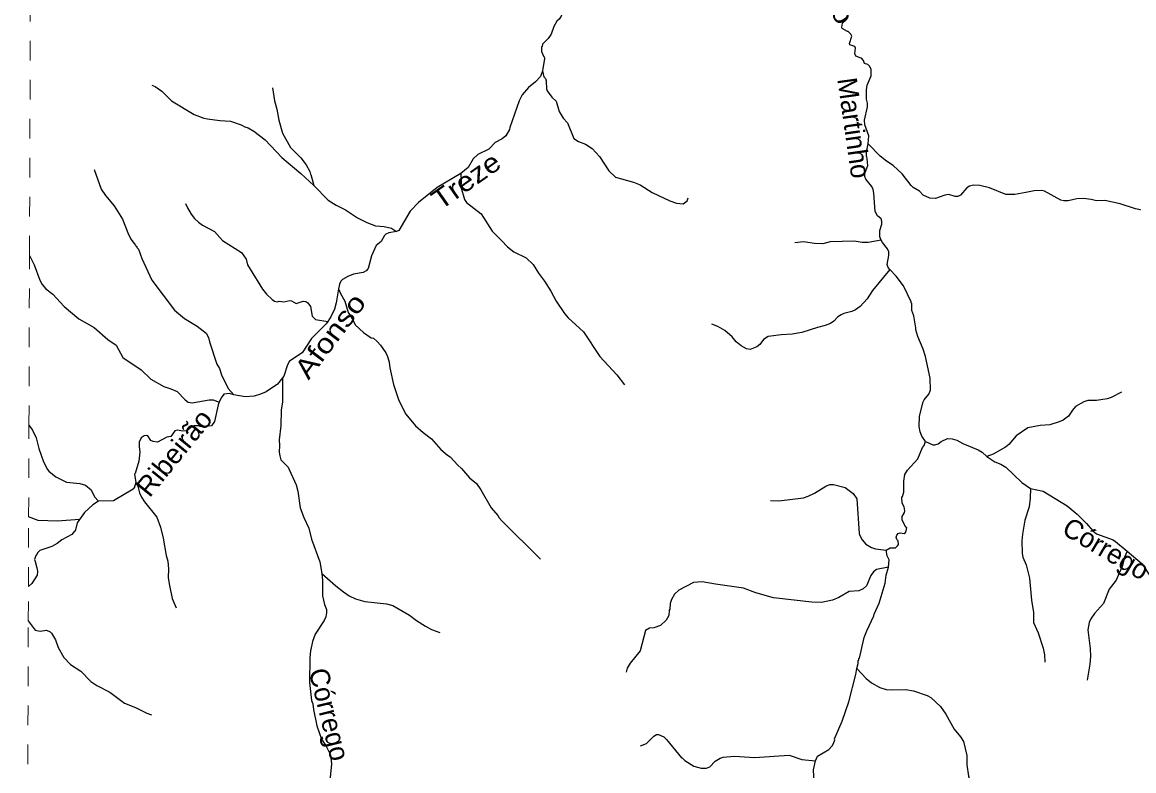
# Model space of a CAD drawing. Extents: x 551.6 to 577.6, y 7567 to 7594.7.
# Drawn here: x 551.61 to 557.32, y 7575.9 to 7579.74 of the extents above; entities that cross this region are included whole.
import ezdxf
from ezdxf.enums import TextEntityAlignment as Align

# ---------------------------------------------------------------- set-up
doc = ezdxf.new("R2010")
doc.units = 0
doc.header["$LTSCALE"] = 0.04
doc.linetypes.add('SHORT_DASHED', pattern=[2.7, 1.5, -1.2])
doc.layers.add('53', color=7, linetype='SHORT_DASHED', lineweight=13)
doc.layers.add('7', color=7, linetype='Continuous', lineweight=25)
doc.layers.add('61', color=7, linetype='Continuous')

msp = doc.modelspace()

# ---------------------------------------------------------------- linework, layer by layer
at = {"layer": '53'}
msp.add_lwpolyline([(551.613, 7567.0572), (551.6165, 7568.1281), (551.6253, 7570.846), (551.6259, 7571.0339), (551.6348, 7573.7652), (551.6406, 7575.5319), (551.6443, 7576.6663), (551.6448, 7576.8423), (551.646, 7577.1998), (551.6475, 7577.6707), (551.6503, 7578.541), (551.6589, 7581.176)], dxfattribs=at)
at = {"layer": '7'}
for points in [[(555.9119, 7579.5547), (555.8885, 7579.5627), (555.8837, 7579.5764), (555.8877, 7579.6038), (555.8845, 7579.6127), (555.8579, 7579.6215), (555.8563, 7579.6271), (555.8692, 7579.665), (555.8644, 7579.6746), (555.8507, 7579.6883), (555.8458, 7579.6883), (555.8193, 7579.7044), (555.8169, 7579.7116), (555.8201, 7579.7326), (555.8386, 7579.747), (555.8483, 7579.7599), (555.8491, 7579.78), (555.8418, 7579.8034), (555.8644, 7579.8404), (555.8644, 7579.8501), (555.8528, 7579.8734)], [(554.3837, 7579.7851), (554.3771, 7579.768), (554.3674, 7579.7527), (554.3562, 7579.7422), (554.3401, 7579.7149), (554.3272, 7579.6762), (554.3103, 7579.6529), (554.2821, 7579.6247), (554.2805, 7579.6127), (554.2773, 7579.6102), (554.2773, 7579.5869), (554.287, 7579.5628), (554.291, 7579.5595), (554.2918, 7579.5507), (554.2818, 7579.4878)], [(555.9532, 7579.1125), (555.9561, 7579.1547), (555.9352, 7579.2111), (555.9336, 7579.2352), (555.9497, 7579.3028), (555.9489, 7579.3221), (555.9432, 7579.3414), (555.944, 7579.3897), (555.9481, 7579.4139), (555.9674, 7579.4622), (555.9674, 7579.4944), (555.9609, 7579.5104), (555.9513, 7579.5201), (555.9336, 7579.5257), (555.9288, 7579.541), (555.9183, 7579.5531), (555.9119, 7579.5547)], [(554.2818, 7579.4878), (554.2725, 7579.4589), (554.2459, 7579.4307), (554.2105, 7579.4026), (554.1783, 7579.364), (554.163, 7579.3342), (554.1147, 7579.1966)], [(554.2818, 7579.4878), (554.2886, 7579.4573), (554.2974, 7579.4477), (554.3015, 7579.4364), (554.3031, 7579.3946), (554.3063, 7579.3849), (554.3296, 7579.3527), (554.3513, 7579.3318), (554.3674, 7579.2787), (554.3884, 7579.2449), (554.4101, 7579.2207), (554.4431, 7579.141), (554.4664, 7579.1257), (554.5027, 7579.1121), (554.5365, 7579.0887), (554.5735, 7579.0485), (554.6226, 7578.9745), (554.6572, 7578.9422), (554.7489, 7578.9165), (554.7827, 7578.902), (554.8439, 7578.8642), (554.9357, 7578.8207)], [(552.2774, 7579.4131), (552.2943, 7579.4066), (552.3297, 7579.3833), (552.378, 7579.3334), (552.4955, 7579.2634), (552.5438, 7579.2448), (552.5631, 7579.2408), (552.6259, 7579.2328), (552.6822, 7579.2295), (552.7361, 7579.2102), (552.7546, 7579.1998), (552.7723, 7579.1958), (552.8013, 7579.178), (552.8585, 7579.133), (552.9454, 7579.0428), (553.0428, 7578.9616), (553.1082, 7578.9001), (553.1828, 7578.8248)], [(552.8971, 7579.4002), (552.9075, 7579.3334), (552.9188, 7579.2915), (552.9285, 7579.2352), (552.9486, 7579.1676), (552.9896, 7579.0936), (553.0419, 7579.0412), (553.0693, 7579.005), (553.0878, 7578.9712), (553.091, 7578.9567), (553.0943, 7578.9551), (553.1082, 7578.9001)], [(554.1147, 7579.1966), (554.1131, 7579.1861), (554.0946, 7579.1539), (554.0745, 7579.1386), (554.0399, 7579.1193), (554.0069, 7579.0863), (553.9497, 7579.0589), (553.9256, 7579.0356), (553.9007, 7578.9921), (553.8627, 7578.9606)], [(555.9819, 7578.8602), (555.9787, 7578.8795), (555.9714, 7578.894), (555.94, 7578.931), (555.9352, 7578.9455), (555.9352, 7578.9608), (555.9505, 7579.0018), (555.9481, 7579.0356), (555.9457, 7579.0469), (555.9432, 7579.0477), (555.9432, 7579.0726), (555.9532, 7579.1125)], [(556.7609, 7578.8642), (556.7046, 7578.8537), (556.6595, 7578.8537), (556.5742, 7578.8875), (556.5259, 7578.8988), (556.4921, 7578.9012), (556.4728, 7578.8964), (556.4583, 7578.8867), (556.4261, 7578.8497), (556.4124, 7578.8433), (556.398, 7578.8433), (556.3666, 7578.8537), (556.3457, 7578.8505), (556.2974, 7578.832), (556.2684, 7578.8352), (556.2346, 7578.8497), (556.2161, 7578.8698), (556.1831, 7578.8899), (556.1726, 7578.8996), (556.1267, 7578.9592), (556.0809, 7579.0018), (556.0463, 7579.0235), (556.0133, 7579.0501), (555.9532, 7579.1125)], [(551.9828, 7578.9809), (552.0174, 7578.8811), (552.04, 7578.8481), (552.085, 7578.7942), (552.1277, 7578.7266), (552.1583, 7578.6477), (552.1711, 7578.6227), (552.1848, 7578.6034), (552.1881, 7578.6034), (552.1913, 7578.5946), (552.1945, 7578.5946), (552.1961, 7578.5889), (552.2009, 7578.5857), (552.2009, 7578.5809), (552.209, 7578.572), (552.2259, 7578.5254), (552.2774, 7578.4143), (552.3933, 7578.2598), (552.4456, 7578.2179), (552.51, 7578.1777), (552.5566, 7578.1423), (552.5679, 7578.1198), (552.5744, 7578.0972)], [(553.8627, 7578.9606), (553.7413, 7578.8891), (553.6455, 7578.8127), (553.6037, 7578.7684), (553.545, 7578.6694), (553.533, 7578.6635)], [(553.8627, 7578.9606), (553.8654, 7578.9212), (553.8631, 7578.8919), (553.8813, 7578.828), (553.8918, 7578.8127), (553.9675, 7578.7547), (554.0238, 7578.6646), (554.0721, 7578.6179), (554.1019, 7578.5841), (554.1341, 7578.5583), (554.1976, 7578.5286), (554.2346, 7578.4948), (554.2612, 7578.4505), (554.2926, 7578.4095), (554.3248, 7578.358), (554.3513, 7578.3057), (554.3948, 7578.2421), (554.4133, 7578.2203), (554.4713, 7578.1672)], [(553.1828, 7578.8248), (553.223, 7578.7982), (553.2713, 7578.7748), (553.3333, 7578.733), (553.3808, 7578.7088), (553.4258, 7578.6928), (553.4693, 7578.6895), (553.5079, 7578.6799), (553.533, 7578.6635)], [(554.9357, 7578.8207), (554.9695, 7578.8095), (555.0033, 7578.8046), (555.0242, 7578.8199), (555.029, 7578.8368)], [(556.0199, 7578.6198), (556.0125, 7578.6364), (556.0125, 7578.6686), (556.0221, 7578.7008), (556.0221, 7578.7169), (556.0189, 7578.729), (556.0004, 7578.7435), (555.9883, 7578.7652), (555.9819, 7578.8602)], [(557.4766, 7578.756), (557.457, 7578.7549), (557.4225, 7578.7587), (557.3243, 7578.7797), (557.2454, 7578.8046), (557.1666, 7578.8223), (557.1247, 7578.8207), (557.0957, 7578.828), (557.0571, 7578.8328), (557.0233, 7578.8312), (556.9782, 7578.8199), (556.9557, 7578.8207), (556.9404, 7578.8247), (556.8567, 7578.8698), (556.843, 7578.873), (556.8044, 7578.8722), (556.7609, 7578.8642)], [(552.4512, 7578.8062), (552.4601, 7578.7845), (552.4802, 7578.7523), (552.4963, 7578.7298), (552.518, 7578.7105), (552.5374, 7578.696), (552.5985, 7578.663), (552.6404, 7578.6171), (552.7385, 7578.5551), (552.7611, 7578.5213), (552.7691, 7578.4932), (552.782, 7578.4706), (552.8456, 7578.3676), (552.8657, 7578.3419), (552.8955, 7578.3153), (552.9075, 7578.3056), (552.9204, 7578.3032), (552.9317, 7578.3064), (552.9542, 7578.3032), (552.9864, 7578.3089), (552.9945, 7578.3073), (553.0186, 7578.2936), (553.054, 7578.3064), (553.0677, 7578.3048), (553.0774, 7578.2984), (553.091, 7578.2791), (553.1007, 7578.2292), (553.1176, 7578.2123), (553.1804, 7578.2022)], [(553.533, 7578.6635), (553.4935, 7578.6573), (553.4789, 7578.6501), (553.4717, 7578.6429), (553.4548, 7578.6115), (553.429, 7578.5922), (553.4049, 7578.5383), (553.3872, 7578.4738), (553.3768, 7578.461), (553.3615, 7578.4529), (553.3132, 7578.4441), (553.2826, 7578.4328), (553.256, 7578.4167), (553.2472, 7578.4079), (553.2399, 7578.3934), (553.2355, 7578.3702), (553.2278, 7578.329)], [(556.0199, 7578.6198), (555.9529, 7578.6074), (555.9223, 7578.6074), (555.8805, 7578.6147), (555.7582, 7578.6099), (555.7195, 7578.6002), (555.6777, 7578.6018), (555.6213, 7578.6099), (555.5771, 7578.6059)], [(556.0631, 7578.4677), (556.0551, 7578.4787), (556.0495, 7578.4948), (556.0591, 7578.5399), (556.0591, 7578.5592), (556.0519, 7578.5753), (556.0253, 7578.6075), (556.0199, 7578.6198)], [(551.6503, 7578.541), (551.6746, 7578.4932), (551.7028, 7578.4143), (551.7148, 7578.3918), (551.7342, 7578.37), (551.7696, 7578.3419), (551.8283, 7578.2791), (551.9032, 7578.2147), (551.982, 7578.1704), (552.0529, 7578.1101), (552.0947, 7578.0803), (552.1293, 7578.0167), (552.2235, 7577.9548), (552.2726, 7577.9065), (552.3394, 7577.8686), (552.3748, 7577.8574), (552.407, 7577.8421), (552.4488, 7577.8002), (552.4649, 7577.789), (552.4842, 7577.7841)], [(556.0631, 7578.4677), (555.9754, 7578.3612), (555.9481, 7578.3177), (555.9119, 7578.2791), (555.8869, 7578.2614), (555.8692, 7578.2533), (555.8274, 7578.2421), (555.8137, 7578.2356), (555.7968, 7578.2252), (555.7759, 7578.2034), (555.7598, 7578.1922), (555.7324, 7578.1809), (555.6922, 7578.1712), (555.6117, 7578.1455), (555.5634, 7578.1374), (555.5055, 7578.1342), (555.4403, 7578.1246), (555.4153, 7578.1093), (555.3968, 7578.0843), (555.3815, 7578.0722), (555.3477, 7578.0586), (555.3284, 7578.0618), (555.301, 7578.0763)], [(556.1976, 7578.1697), (556.1863, 7578.2308), (556.1766, 7578.2582), (556.1766, 7578.2944), (556.1734, 7578.2968), (556.1734, 7578.3032), (556.1332, 7578.3853), (556.097, 7578.4336), (556.0631, 7578.4677)], [(553.2355, 7578.3702), (553.2456, 7578.3451), (553.2681, 7578.3065), (553.285, 7578.2485), (553.3091, 7578.2099), (553.3212, 7578.1841), (553.3631, 7578.1455), (553.4025, 7578.1189), (553.4146, 7578.1157), (553.4331, 7578.0996), (553.4508, 7578.0811), (553.4781, 7578.0409), (553.487, 7578.0216), (553.495, 7577.9926), (553.4983, 7577.9636), (553.5176, 7577.8783), (553.5457, 7577.7962), (553.5804, 7577.7262), (553.6303, 7577.6674), (553.6697, 7577.632), (553.7123, 7577.6006), (553.7606, 7577.5459), (553.7952, 7577.517)], [(553.2278, 7578.329), (553.2238, 7578.2968), (553.215, 7578.2646), (553.1973, 7578.2284), (553.1804, 7578.2022)], [(553.1804, 7578.2022), (553.1723, 7578.1897), (553.0975, 7578.1149), (553.0492, 7578.0417), (552.9848, 7577.9982), (552.9743, 7577.9797), (552.9542, 7577.9218), (552.9478, 7577.9124)], [(554.4713, 7578.1672), (554.4914, 7578.1487), (554.5767, 7578.0224), (554.6628, 7577.929), (554.7031, 7577.8775)], [(555.301, 7578.0763), (555.2761, 7578.0972), (555.2543, 7578.123), (555.2181, 7578.156), (555.1811, 7578.1769), (555.1505, 7578.1874)], [(556.2473, 7577.5872), (556.2273, 7577.6143), (556.2185, 7577.6353), (556.2137, 7577.6642), (556.2153, 7577.7165), (556.2346, 7577.7898), (556.2394, 7577.8002), (556.2644, 7577.8284), (556.2716, 7577.8493), (556.27, 7577.9121), (556.2467, 7578.0216), (556.2346, 7578.0602), (556.2072, 7578.1246), (556.1976, 7578.1584), (556.1976, 7578.1697)], [(552.5744, 7578.0972), (552.6114, 7577.9829), (552.6242, 7577.9604), (552.6347, 7577.9282), (552.6701, 7577.859), (552.6991, 7577.8264)], [(552.9478, 7577.9124), (552.922, 7577.8799), (552.8641, 7577.8413), (552.8351, 7577.8284), (552.8029, 7577.8187), (552.7563, 7577.8155), (552.6991, 7577.8264)], [(552.9478, 7577.9124), (552.9478, 7577.7882), (552.9413, 7577.7495), (552.9397, 7577.6675), (552.9309, 7577.5942), (552.9333, 7577.5661), (552.9317, 7577.5323), (552.9349, 7577.5129), (552.9397, 7577.4928), (552.9768, 7577.455), (552.9832, 7577.4437), (553.0178, 7577.3649), (553.0266, 7577.3311), (553.0395, 7577.2457), (553.0572, 7577.1975), (553.083, 7577.1427), (553.0975, 7577.0864), (553.1393, 7576.9689), (553.1501, 7576.9091)], [(552.4842, 7577.7841), (552.5728, 7577.8002), (552.5921, 7577.7994), (552.6233, 7577.788)], [(552.6991, 7577.8264), (552.6758, 7577.8332), (552.6468, 7577.83), (552.6331, 7577.8107), (552.6233, 7577.788)], [(557.2527, 7577.8397), (557.1988, 7577.8123), (557.1794, 7577.8059), (557.1247, 7577.797), (557.0796, 7577.797), (557.0587, 7577.7906), (557.0168, 7577.7656), (557.0008, 7577.7479), (556.9798, 7577.7165), (556.9525, 7577.6956), (556.9332, 7577.6868), (556.8849, 7577.6723), (556.835, 7577.669), (556.7722, 7577.6562), (556.7118, 7577.6159), (556.674, 7577.5709), (556.6579, 7577.5572), (556.5935, 7577.5218), (556.5618, 7577.5095)], [(552.6233, 7577.788), (552.6178, 7577.7753), (552.6001, 7577.6884), (552.584, 7577.6674), (552.5551, 7577.6626), (552.5261, 7577.6642), (552.518, 7577.6674), (552.4939, 7577.6666), (552.4778, 7577.6578), (552.4593, 7577.6409), (552.4376, 7577.6401), (552.4086, 7577.6441), (552.3957, 7577.6417), (552.3748, 7577.6127), (552.3555, 7577.6087)], [(551.6475, 7577.6707), (551.6649, 7577.6449), (551.6842, 7577.6047), (551.6987, 7577.55), (551.7213, 7577.4824), (551.7422, 7577.4437), (551.7502, 7577.4349), (551.7857, 7577.4059), (551.8404, 7577.3777), (551.908, 7577.3713), (551.937, 7577.3632), (551.9659, 7577.3391), (551.9836, 7577.3021), (552.0043, 7577.2799)], [(552.3555, 7577.6087), (552.3072, 7577.5837), (552.2854, 7577.5862), (552.2726, 7577.591), (552.2581, 7577.6151), (552.2525, 7577.6167), (552.2388, 7577.6159), (552.2234, 7577.6047), (552.2122, 7577.5829), (552.2122, 7577.5612), (552.217, 7577.5323), (552.2114, 7577.4856), (552.1929, 7577.4228), (552.1897, 7577.4196), (552.1952, 7577.3762)], [(556.1283, 7577.3037), (556.1348, 7577.3262), (556.1348, 7577.3826), (556.1412, 7577.4164), (556.1541, 7577.4389), (556.2072, 7577.4968), (556.2314, 7577.5564), (556.2394, 7577.566), (556.2473, 7577.5872)], [(556.2473, 7577.5872), (556.2845, 7577.5693), (556.2942, 7577.5693), (556.311, 7577.5741), (556.3263, 7577.5862), (556.3601, 7577.6014), (556.3827, 7577.5998), (556.4068, 7577.5934), (556.439, 7577.5765), (556.5171, 7577.5435), (556.5372, 7577.5322), (556.5618, 7577.5095)], [(553.7952, 7577.517), (553.8081, 7577.5081), (553.8475, 7577.4646), (553.8661, 7577.4485), (553.9071, 7577.4002), (553.9433, 7577.3705), (553.9658, 7577.3391), (554.0182, 7577.2457), (554.0536, 7577.2071), (554.06, 7577.1942), (554.0729, 7577.1789), (554.2709, 7576.9826)], [(556.5618, 7577.5095), (556.6016, 7577.4815), (556.6338, 7577.4695), (556.6587, 7577.4542), (556.7408, 7577.3769), (556.7848, 7577.346)], [(552.1952, 7577.3762), (552.1864, 7577.3471), (552.1816, 7577.3455), (552.1816, 7577.3415), (552.0818, 7577.2819), (552.0043, 7577.2799)], [(552.1952, 7577.3762), (552.2066, 7577.3568), (552.2146, 7577.323), (552.2243, 7577.3005), (552.2396, 7577.2763), (552.3031, 7577.1991), (552.3224, 7577.1476), (552.3361, 7577.0912), (552.3506, 7577.0011), (552.3595, 7576.9721), (552.3635, 7576.9335), (552.3619, 7576.8868), (552.3683, 7576.8482), (552.382, 7576.7806), (552.4029, 7576.7331)], [(555.4515, 7577.2844), (555.4942, 7577.2827), (555.6213, 7577.298), (555.6439, 7577.3053), (555.6777, 7577.3222), (555.7356, 7577.3576), (555.7557, 7577.3664), (555.7743, 7577.3656), (555.8354, 7577.3503), (555.8757, 7577.319), (555.8941, 7577.2924), (555.907, 7577.1154), (555.9094, 7577.1041), (555.9215, 7577.0816), (555.94, 7577.0606), (555.969, 7577.0429), (555.9899, 7577.0365), (556.0453, 7577.0294)], [(556.7848, 7577.346), (556.7835, 7577.2956), (556.7786, 7577.2522), (556.7569, 7577.183), (556.7448, 7577.1105), (556.7416, 7577.0767), (556.7432, 7577.0115), (556.7464, 7576.993), (556.7625, 7576.9544), (556.7802, 7576.8852), (556.7907, 7576.7725), (556.8012, 7576.7097), (556.8012, 7576.6582), (556.8245, 7576.6051), (556.8511, 7576.5263), (556.8575, 7576.4924), (556.8591, 7576.4546)], [(556.7848, 7577.346), (556.8511, 7577.331), (556.9734, 7577.257), (557.0249, 7577.2136), (557.0732, 7577.1653), (557.1046, 7577.129), (557.1247, 7577.1137), (557.21, 7577.0815)], [(556.0453, 7577.0294), (556.0654, 7577.0413), (556.0921, 7577.0413), (556.1034, 7577.0518), (556.1074, 7577.059), (556.1058, 7577.0767), (556.0994, 7577.0832), (556.0962, 7577.096), (556.0994, 7577.1057), (556.1058, 7577.1146), (556.1171, 7577.1178), (556.1364, 7577.1153), (556.1444, 7577.1202), (556.1477, 7577.129), (556.1501, 7577.1451), (556.1461, 7577.1476), (556.1267, 7577.1838), (556.1275, 7577.2023), (556.1396, 7577.2216), (556.1412, 7577.2313), (556.1364, 7577.2506), (556.1267, 7577.2699), (556.1251, 7577.2997), (556.1283, 7577.3037)], [(552.0043, 7577.2799), (551.9756, 7577.261), (551.9329, 7577.2216), (551.9063, 7577.1859)], [(551.9063, 7577.1859), (551.7937, 7577.1781), (551.6955, 7577.1813), (551.646, 7577.1998)], [(551.9063, 7577.1859), (551.8951, 7577.1701), (551.8838, 7577.1266), (551.8806, 7577.1266), (551.8677, 7577.1089), (551.8162, 7577.0815), (551.7921, 7577.063), (551.7655, 7577.0485), (551.7036, 7577.0268), (551.6907, 7577.0155), (551.6859, 7577.0027), (551.6826, 7577.0019), (551.6762, 7576.981), (551.6786, 7576.9705)], [(557.21, 7577.0815), (557.2221, 7577.0743), (557.2811, 7577.024)], [(556.0567, 7576.9427), (556.0607, 7576.9802), (556.0495, 7576.9995), (556.0453, 7577.0294)], [(557.2811, 7577.024), (557.2679, 7576.993), (557.2575, 7576.9512), (557.2245, 7576.8747), (557.1891, 7576.8289), (557.1593, 7576.7564), (557.1134, 7576.7049), (557.0949, 7576.6776), (557.0869, 7576.6582), (557.0796, 7576.6212), (557.0917, 7576.5246), (557.0925, 7576.4844), (557.0901, 7576.4442), (557.0764, 7576.3629)], [(557.2811, 7577.024), (557.3581, 7576.9584), (557.4166, 7576.8677)], [(551.6786, 7576.9705), (551.6883, 7576.9383), (551.6907, 7576.9222), (551.6891, 7576.9013), (551.6617, 7576.8578), (551.6448, 7576.8423)], [(556.0567, 7576.9427), (555.9948, 7576.9294), (555.9803, 7576.9182), (555.9666, 7576.8997), (555.9433, 7576.8465), (555.9272, 7576.8304), (555.9046, 7576.8208), (555.8547, 7576.8168), (555.8016, 7576.7862), (555.7694, 7576.7725), (555.7131, 7576.7612), (555.6632, 7576.7628), (555.4668, 7576.7854), (555.3767, 7576.8111), (555.3123, 7576.8337), (555.169, 7576.8554)], [(555.9835, 7576.7017), (556.0084, 7576.758), (556.0302, 7576.8256), (556.0398, 7576.8594), (556.0446, 7576.9013), (556.0567, 7576.9427)], [(553.1501, 7576.9091), (553.1538, 7576.8739), (553.1538, 7576.7951), (553.1643, 7576.75), (553.1747, 7576.7242), (553.1747, 7576.7081), (553.1707, 7576.6872), (553.1619, 7576.6679), (553.116, 7576.5987), (553.1015, 7576.5609), (553.0943, 7576.519), (553.091, 7576.5142), (553.0878, 7576.4764), (553.0862, 7576.3508), (553.0975, 7576.2582), (553.1039, 7576.2414), (553.1071, 7576.2124), (553.1248, 7576.1287), (553.1482, 7576.0595), (553.1723, 7576.0241), (553.194, 7575.979)], [(553.1501, 7576.9091), (553.2214, 7576.8457), (553.2609, 7576.816), (553.2906, 7576.7958), (553.3228, 7576.7797), (553.3711, 7576.7661), (553.4822, 7576.7548), (553.5144, 7576.7459), (553.5997, 7576.6952), (553.6359, 7576.6679), (553.6818, 7576.6389), (553.7123, 7576.6228), (553.755, 7576.6067)], [(555.169, 7576.8554), (555.1014, 7576.8667), (555.0564, 7576.8626), (554.9807, 7576.8248), (554.9598, 7576.8031), (554.9437, 7576.7757), (554.9372, 7576.7564), (554.9356, 7576.7258), (554.9324, 7576.721), (554.9292, 7576.6936), (554.9163, 7576.6695), (554.8866, 7576.6421), (554.8536, 7576.6309), (554.831, 7576.6284), (554.8101, 7576.618), (554.7827, 7576.5134), (554.732, 7576.4498), (554.7167, 7576.4232), (554.7103, 7576.4031)], [(551.6443, 7576.6663), (551.6794, 7576.6188), (551.7052, 7576.6132), (551.7374, 7576.6196), (551.7559, 7576.6107), (551.7639, 7576.6027), (551.784, 7576.5697), (551.7977, 7576.5295), (551.8259, 7576.4788), (551.8605, 7576.4433), (551.9144, 7576.4079), (551.9651, 7576.3564), (551.9965, 7576.3355), (552.0625, 7576.3017), (552.1382, 7576.2437), (552.1945, 7576.2228), (552.2525, 7576.193), (552.2758, 7576.185)], [(555.895, 7576.4216), (555.9014, 7576.4482), (555.9014, 7576.4627), (555.9046, 7576.4643), (555.9046, 7576.4739), (555.9078, 7576.4755), (555.9328, 7576.581), (555.9449, 7576.6148), (555.9819, 7576.692), (555.9835, 7576.7017)], [(555.6826, 7575.9495), (555.693, 7575.9725), (555.7501, 7576.0071), (555.7678, 7576.0256), (555.775, 7576.0385), (555.7815, 7576.0562), (555.7806, 7576.0611), (555.8193, 7576.1528), (555.8531, 7576.251), (555.8901, 7576.391), (555.895, 7576.4216)], [(555.895, 7576.4216), (555.9416, 7576.3709), (555.969, 7576.3492), (556.0125, 7576.325), (556.0447, 7576.3154), (556.0785, 7576.3122), (556.1461, 7576.3138), (556.1847, 7576.3073), (556.2547, 7576.2832), (556.2748, 7576.2735), (556.3239, 7576.2269), (556.3505, 7576.1882), (556.3939, 7576.111), (556.4269, 7576.0723), (556.4422, 7576.0482), (556.4583, 7575.9758), (556.4583, 7575.9275), (556.468, 7575.8695), (556.4865, 7575.8116), (556.5203, 7575.7504)], [(554.7852, 7576.0257), (554.8149, 7576.0385), (554.8536, 7576.0755), (554.8664, 7576.0836), (554.8777, 7576.0844), (554.9035, 7576.0723), (554.9179, 7576.0579), (554.9944, 7575.9645), (554.9992, 7575.9637), (555.0129, 7575.95), (555.058, 7575.921), (555.0966, 7575.9114), (555.1224, 7575.9114), (555.1401, 7575.9178), (555.1674, 7575.9468), (555.1932, 7575.9629), (555.2085, 7575.9677), (555.2672, 7575.9733), (555.3686, 7575.9661), (555.5465, 7575.9774), (555.6117, 7575.9556), (555.6826, 7575.9495)], [(553.194, 7575.979), (553.1989, 7575.9339), (553.1892, 7575.8293), (553.1915, 7575.7752), (553.2069, 7575.7021), (553.2198, 7575.6587), (553.2745, 7575.5058), (553.2858, 7575.4269), (553.3099, 7575.3255), (553.3164, 7575.1179), (553.3051, 7575.0068), (553.2786, 7574.9174)], [(555.6567, 7575.7231), (555.6664, 7575.7681), (555.6744, 7575.8695), (555.6728, 7575.9033), (555.6826, 7575.9495)]]:
    msp.add_lwpolyline(points, dxfattribs=at)

# ---------------------------------------------------------------- texts
at = {"layer": '61'}
for s, rotation, width, p in [('São', 298.628, 1.15, (555.7331, 7579.8357)), ('Treze', 35.119, 1.15, (553.9186, 7578.8831)), ('Afonso', 53.011, 1.2, (553.2322, 7578.0977)), ('Ribeirão', 50.926, 1.05, (552.4309, 7577.4971))]:
    msp.add_text(s, height=0.1, rotation=rotation, dxfattribs=dict(at, width=width)).set_placement(p, align=Align.CENTER)
for s, rotation, p in [('Martinho', 278.076, (555.8307, 7579.1878)), ('Córrego', 329.44, (557.1475, 7576.9939)), ('Córrego', 283.803, (553.1398, 7576.1755))]:
    msp.add_text(s, height=0.1, rotation=rotation, dxfattribs=at).set_placement(p, align=Align.CENTER)

doc.saveas('drawing.dxf')
